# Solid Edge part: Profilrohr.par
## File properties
Username: ahadarics
Dokumentum tartalom típus: 0
Author: ahadarics
Last saved by: ahadarics
Revision: 92
Sűrűség: 0,000 kg/m^3
Pontosság: 0,990
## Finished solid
Body 1: solid body, 6 faces, 6 edges, 0 vertices.
  Faces by surface: cone 2, cylinder 2, plane 2
  Edges by curve: circle 6
Bounding box of the edges (mm): 21.270 x 21.270 x 1032.000, from (-10.635, -10.635, -1011) to (10.635, 10.635, 21).
Cylindrical faces by radius (mm): R10 x1, R10.635 x1
Conical faces (half-angle, radius in mm at the cone's reference point): 15 deg R10.067 x2
Planar faces by outward normal: +z 1, -z 1
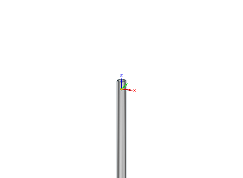
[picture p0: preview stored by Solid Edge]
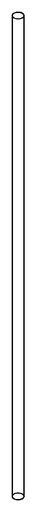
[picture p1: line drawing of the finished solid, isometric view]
